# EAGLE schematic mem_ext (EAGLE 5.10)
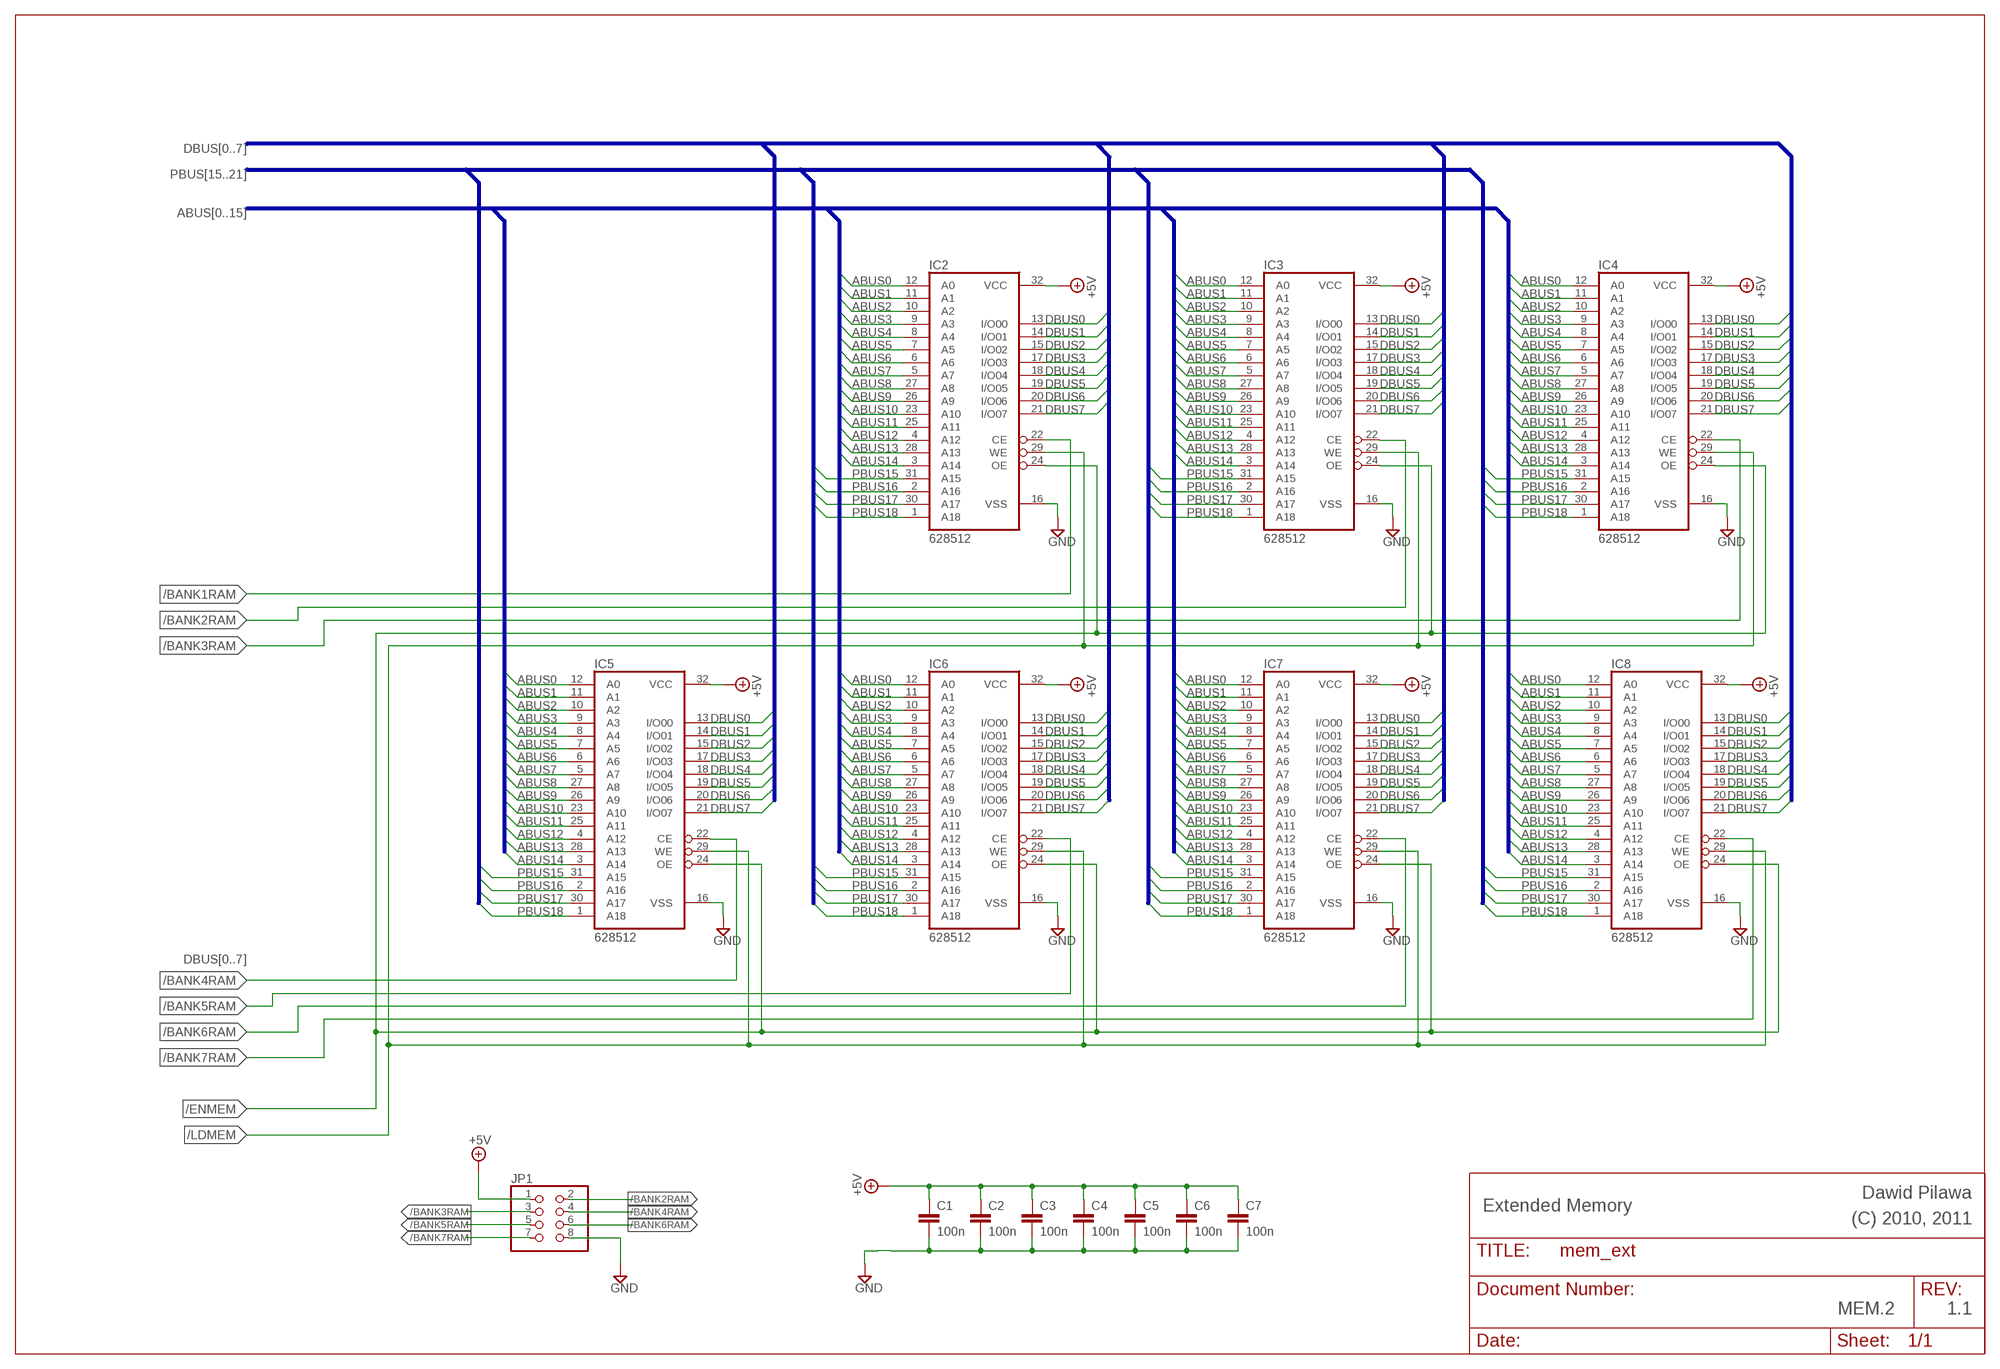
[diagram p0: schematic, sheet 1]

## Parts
C1  100n  C-EU050-024X044  [C050-024X044]
C2  100n  C-EU050-024X044  [C050-024X044]
C3  100n  C-EU050-024X044  [C050-024X044]
C4  100n  C-EU050-024X044  [C050-024X044]
C5  100n  C-EU050-024X044  [C050-024X044]
C6  100n  C-EU050-024X044  [C050-024X044]
C7  100n  C-EU050-024X044  [C050-024X044]
IC2  628512  HM628512A_DIL32  [DIL32]
IC3  628512  HM628512A_DIL32  [DIL32]
IC4  628512  HM628512A_DIL32  [DIL32]
IC5  628512  HM628512A_DIL32  [DIL32]
IC6  628512  HM628512A_DIL32  [DIL32]
IC7  628512  HM628512A_DIL32  [DIL32]
IC8  628512  HM628512A_DIL32  [DIL32]
JP1  PINHD-2X4  [2X04]

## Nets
+5V: C1.1 C2.1 C3.1 C4.1 C5.1 C6.1 C7.1 IC2.32(VCC) IC3.32(VCC) IC4.32(VCC) IC5.32(VCC) IC6.32(VCC) IC7.32(VCC) IC8.32(VCC) JP1.1
/BANK1RAM: IC2.22(CE)
/BANK2RAM: IC3.22(CE) JP1.2
/BANK3RAM: IC4.22(CE) JP1.3
/BANK4RAM: IC5.22(CE) JP1.4
/BANK5RAM: IC6.22(CE) JP1.5
/BANK6RAM: IC7.22(CE) JP1.6
/BANK7RAM: IC8.22(CE) JP1.7
/ENMEM: IC2.24(OE) IC3.24(OE) IC4.24(OE) IC5.24(OE) IC6.24(OE) IC7.24(OE) IC8.24(OE)
/LDMEM: IC2.29(WE) IC3.29(WE) IC4.29(WE) IC5.29(WE) IC6.29(WE) IC7.29(WE) IC8.29(WE)
ABUS0: IC2.12(A0) IC3.12(A0) IC4.12(A0) IC5.12(A0) IC6.12(A0) IC7.12(A0) IC8.12(A0)
ABUS1: IC2.11(A1) IC3.11(A1) IC4.11(A1) IC5.11(A1) IC6.11(A1) IC7.11(A1) IC8.11(A1)
ABUS2: IC2.10(A2) IC3.10(A2) IC4.10(A2) IC5.10(A2) IC6.10(A2) IC7.10(A2) IC8.10(A2)
ABUS3: IC2.9(A3) IC3.9(A3) IC4.9(A3) IC5.9(A3) IC6.9(A3) IC7.9(A3) IC8.9(A3)
ABUS4: IC2.8(A4) IC3.8(A4) IC4.8(A4) IC5.8(A4) IC6.8(A4) IC7.8(A4) IC8.8(A4)
ABUS5: IC2.7(A5) IC3.7(A5) IC4.7(A5) IC5.7(A5) IC6.7(A5) IC7.7(A5) IC8.7(A5)
ABUS6: IC2.6(A6) IC3.6(A6) IC4.6(A6) IC5.6(A6) IC6.6(A6) IC7.6(A6) IC8.6(A6)
ABUS7: IC2.5(A7) IC3.5(A7) IC4.5(A7) IC5.5(A7) IC6.5(A7) IC7.5(A7) IC8.5(A7)
ABUS8: IC2.27(A8) IC3.27(A8) IC4.27(A8) IC5.27(A8) IC6.27(A8) IC7.27(A8) IC8.27(A8)
ABUS9: IC2.26(A9) IC3.26(A9) IC4.26(A9) IC5.26(A9) IC6.26(A9) IC7.26(A9) IC8.26(A9)
ABUS10: IC2.23(A10) IC3.23(A10) IC4.23(A10) IC5.23(A10) IC6.23(A10) IC7.23(A10) IC8.23(A10)
ABUS11: IC2.25(A11) IC3.25(A11) IC4.25(A11) IC5.25(A11) IC6.25(A11) IC7.25(A11) IC8.25(A11)
ABUS12: IC2.4(A12) IC3.4(A12) IC4.4(A12) IC5.4(A12) IC6.4(A12) IC7.4(A12) IC8.4(A12)
ABUS13: IC2.28(A13) IC3.28(A13) IC4.28(A13) IC5.28(A13) IC6.28(A13) IC7.28(A13) IC8.28(A13)
ABUS14: IC2.3(A14) IC3.3(A14) IC4.3(A14) IC5.3(A14) IC6.3(A14) IC7.3(A14) IC8.3(A14)
DBUS0: IC2.13(I/O00) IC3.13(I/O00) IC4.13(I/O00) IC5.13(I/O00) IC6.13(I/O00) IC7.13(I/O00) IC8.13(I/O00)
DBUS1: IC2.14(I/O01) IC3.14(I/O01) IC4.14(I/O01) IC5.14(I/O01) IC6.14(I/O01) IC7.14(I/O01) IC8.14(I/O01)
DBUS2: IC2.15(I/O02) IC3.15(I/O02) IC4.15(I/O02) IC5.15(I/O02) IC6.15(I/O02) IC7.15(I/O02) IC8.15(I/O02)
DBUS3: IC2.17(I/O03) IC3.17(I/O03) IC4.17(I/O03) IC5.17(I/O03) IC6.17(I/O03) IC7.17(I/O03) IC8.17(I/O03)
DBUS4: IC2.18(I/O04) IC3.18(I/O04) IC4.18(I/O04) IC5.18(I/O04) IC6.18(I/O04) IC7.18(I/O04) IC8.18(I/O04)
DBUS5: IC2.19(I/O05) IC3.19(I/O05) IC4.19(I/O05) IC5.19(I/O05) IC6.19(I/O05) IC7.19(I/O05) IC8.19(I/O05)
DBUS6: IC2.20(I/O06) IC3.20(I/O06) IC4.20(I/O06) IC5.20(I/O06) IC6.20(I/O06) IC7.20(I/O06) IC8.20(I/O06)
DBUS7: IC2.21(I/O07) IC3.21(I/O07) IC4.21(I/O07) IC5.21(I/O07) IC6.21(I/O07) IC7.21(I/O07) IC8.21(I/O07)
GND: C1.2 C2.2 C3.2 C4.2 C5.2 C6.2 C7.2 IC2.16(VSS) IC3.16(VSS) IC4.16(VSS) IC5.16(VSS) IC6.16(VSS) IC7.16(VSS) IC8.16(VSS) JP1.8
PBUS15: IC2.31(A15) IC3.31(A15) IC4.31(A15) IC5.31(A15) IC6.31(A15) IC7.31(A15) IC8.31(A15)
PBUS16: IC2.2(A16) IC3.2(A16) IC4.2(A16) IC5.2(A16) IC6.2(A16) IC7.2(A16) IC8.2(A16)
PBUS17: IC2.30(A17) IC3.30(A17) IC4.30(A17) IC5.30(A17) IC6.30(A17) IC7.30(A17) IC8.30(A17)
PBUS18: IC2.1(A18) IC3.1(A18) IC4.1(A18) IC5.1(A18) IC6.1(A18) IC7.1(A18) IC8.1(A18)

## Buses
ABUS[0..15]
PBUS[15..21]
DBUS[0..7]

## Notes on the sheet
- Dawid Pilawa
- Extended Memory | (C) 2010, 2011
- MEM.2 | 1.1

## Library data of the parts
C1-C7 = rcl:C-EU: CAPACITOR, European symbol
IC2-IC8 = hitachi_sram_hm628512a-series_rev1:HM628512A_DIL32: 4M SRAM 512kword x 8bit
JP1 = pinhead:PINHD-2X4: PIN HEADER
